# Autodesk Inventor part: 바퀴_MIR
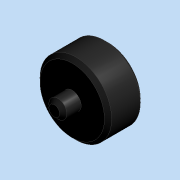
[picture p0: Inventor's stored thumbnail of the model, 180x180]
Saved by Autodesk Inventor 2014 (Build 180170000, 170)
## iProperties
Created: 2015-05
Part Number: 바퀴_MIR
Material: 일반
Vendor: CBT Solutions
Document SubType Name: 모델링
Designer: Administrator
Appearance: 기본값
Company: 한국ATC센터
Author: KYOUNG IL JANG
Comments: 파생
d0: 1.000 ul
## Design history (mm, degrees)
derived "바퀴.ipt" dims count "d0" = 1
feature "솔리드1::바퀴.ipt" dims count "d0" = 1
tag "피쳐 태그1"
node "솔리드1"
